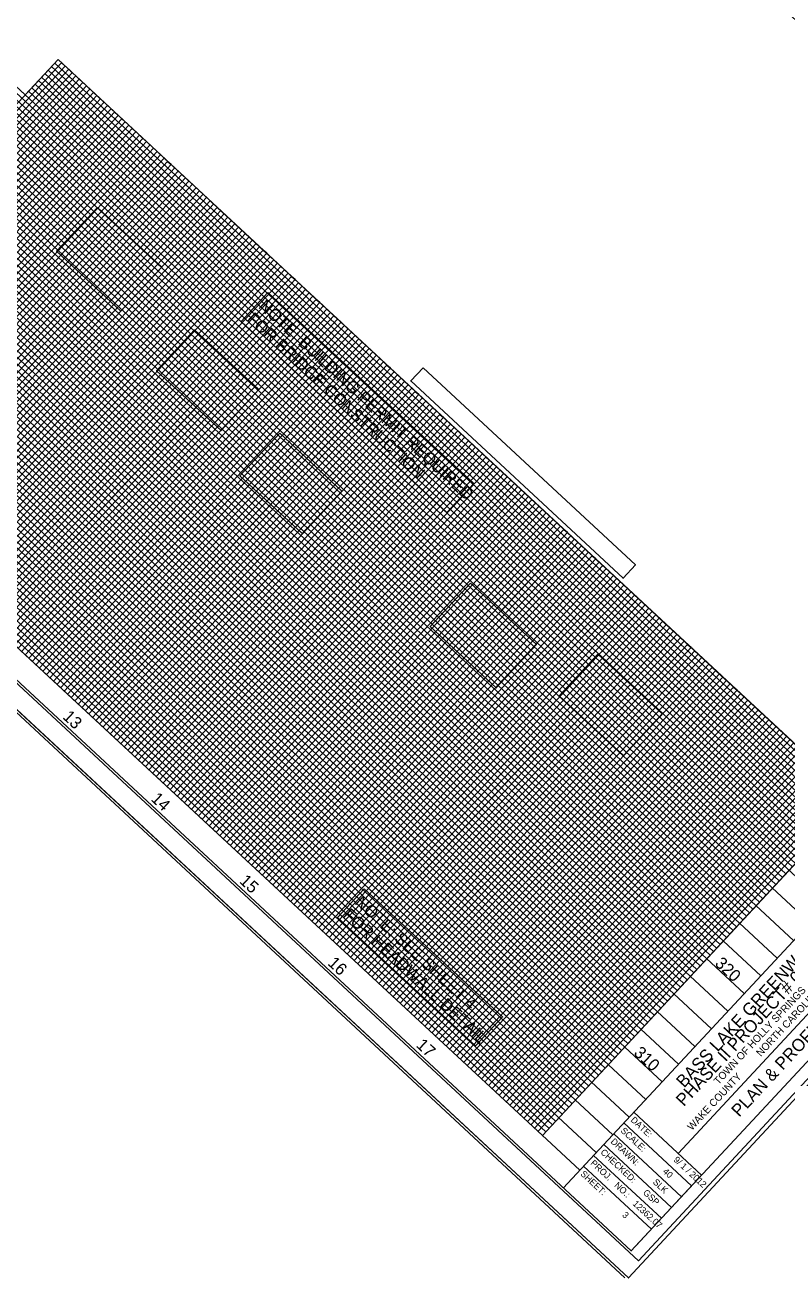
# Model space of a CAD drawing. Extents: x 2057696 to 2061410, y 685900 to 689434.
# Drawn here: x 2058183 to 2058814, y 687875 to 688913 of the extents above; entities that cross this region are included whole.
import ezdxf

# ---------------------------------------------------------------- set-up
doc = ezdxf.new("R2010")
doc.units = 0
for name, color, linetype in [('Default', 7, 'Continuous'), ('Exist Vertical Profile Vertical Axis Label', 7, 'Continuous'), ('Prop Approach Slab', 7, 'Continuous'), ('Prop Boundary Buffer Zone 2', 7, 'Continuous'), ('Prop SS Cut Line', 7, 'Continuous'), ('Prop Vertical Profile Curve Label', 7, 'Continuous'), ('Sheet Cutting Line CELL', 7, 'Continuous'), ('Sheet Plan CELL', 7, 'Continuous'), ('Sheet Plot Border Inside CELL', 7, 'Continuous'), ('Sheet Plot Border Outside CELL', 7, 'Continuous'), ('Sheet Profile Grid Major CELL', 7, 'Continuous')]:
    doc.layers.add(name, color=color, linetype=linetype)

msp = doc.modelspace()

# ---------------------------------------------------------------- linework, layer by layer
at = {"layer": 'Default'}
for p, q in [((2058239.6, 688857.6), (2058268.9, 688830.4)), ((2058268.9, 688830.4), (2058010.2, 688552)), ((2058298.2, 688803.1), (2058327.5, 688775.9)), ((2057696.3, 688791.9), (2058682.8, 687875)), ((2058342.2, 688762.3), (2058083.5, 688484)), ((2058356.8, 688748.7), (2058386.1, 688721.4)), ((2057754, 688735.6), (2058679.9, 687875)), ((2057806.1, 688714.4), (2058685.1, 687897.4)), ((2058415.4, 688694.2), (2058399.7, 688677.3)), ((2058415.4, 688694.2), (2058444.7, 688667)), ((2058377.4, 688653.3), (2058356.1, 688630.4)), ((2058474, 688639.7), (2058503.3, 688612.5)), ((2058488.7, 688626.1), (2058472.9, 688609.2)), ((2058324.6, 688596.5), (2058156.7, 688415.9)), ((2058450.5, 688585.1), (2058419.2, 688551.5)), ((2058532.6, 688585.3), (2058561.9, 688558.1)), ((2059200.9, 688564.9), (2058628.8, 687949.4)), ((2058561.9, 688558.1), (2058546.2, 688541.1)), ((2058591.2, 688530.8), (2058620.5, 688503.6)), ((2058386.4, 688516.1), (2058229.9, 688347.8)), ((2058523.9, 688517.2), (2058303.2, 688279.7)), ((2059257, 688512.7), (2058684.9, 687897.2)), ((2058635.1, 688490), (2058577, 688427.4)), ((2058649.8, 688476.4), (2058679.1, 688449.1)), ((2058708.4, 688421.9), (2058669.9, 688380.5)), ((2058708.4, 688421.9), (2058737.7, 688394.7)), ((2058543.7, 688391.6), (2058376.4, 688211.6)), ((2058781.6, 688353.8), (2058556.5, 688111.6)), ((2058637.8, 688346), (2058483.3, 688179.7)), ((2058854.9, 688285.7), (2058596.2, 688007.4)), ((2058461, 688155.7), (2058449.7, 688143.6)), ((2058724.1, 687978.2), (2058897.9, 688165.2)), ((2058533.8, 688087.2), (2058522.9, 688075.5)), ((2058743.4, 687960.2), (2058687.3, 688012.4)), ((2058735.1, 687951.2), (2058679, 688003.4)), ((2058726.8, 687942.3), (2058670.7, 687994.4)), ((2058718.5, 687933.3), (2058662.4, 687985.5)), ((2058710.2, 687924.4), (2058654, 687976.5)), ((2058701.8, 687915.4), (2058645.7, 687967.6)), ((2058743.4, 687960.2), (2058688.9, 687901.7))]:
    msp.add_line(p, q, dxfattribs=at)
for points in [[(2057696.3, 688791.9), (2058682.8, 687875), (2059279.2, 688516.6), (2058292.7, 689433.5)], [(2057714.8, 688796.5), (2058691.1, 687889.2), (2059265.7, 688507.4), (2058289.4, 689414.7)]]:
    msp.add_lwpolyline(points, close=True, dxfattribs=at)
at = {"layer": 'Exist Vertical Profile Vertical Axis Label'}
for points in [[(2057954.5, 688603.8), (2058213.2, 688882.1), (2058216.2, 688879.4), (2057957.5, 688601.1)], [(2057960.4, 688598.3), (2058219.1, 688876.7), (2058222, 688873.9), (2057963.3, 688595.6)], [(2057969.2, 688590.2), (2058227.9, 688868.5), (2058230.8, 688865.8), (2057972.1, 688587.4)], [(2057975, 688584.7), (2058233.8, 688863.1), (2058236.7, 688860.3), (2057978, 688582)], [(2057983.8, 688576.5), (2058242.5, 688854.9), (2058245.5, 688852.2), (2057986.8, 688573.8)], [(2057989.7, 688571.1), (2058248.4, 688849.4), (2058251.3, 688846.7), (2057992.6, 688568.4)], [(2057998.5, 688562.9), (2058257.2, 688841.3), (2058260.1, 688838.5), (2058001.4, 688560.2)], [(2058004.3, 688557.5), (2058263.1, 688835.8), (2058266, 688833.1), (2058007.3, 688554.8)], [(2058013.1, 688549.3), (2058271.8, 688827.7), (2058274.8, 688824.9), (2058016.1, 688546.6)], [(2058019, 688543.9), (2058277.7, 688822.2), (2058280.6, 688819.5), (2058021.9, 688541.1)], [(2058027.8, 688535.7), (2058286.5, 688814), (2058289.4, 688811.3), (2058030.7, 688533)], [(2058033.6, 688530.3), (2058292.3, 688808.6), (2058295.3, 688805.9), (2058036.6, 688527.5)], [(2058042.4, 688522.1), (2058301.1, 688800.4), (2058304.1, 688797.7), (2058045.4, 688519.4)], [(2058048.3, 688516.6), (2058307, 688795), (2058309.9, 688792.3), (2058051.2, 688513.9)], [(2058057.1, 688508.5), (2058315.8, 688786.8), (2058318.7, 688784.1), (2058060, 688505.7)], [(2058062.9, 688503), (2058321.6, 688781.4), (2058324.6, 688778.6), (2058065.9, 688500.3)], [(2058071.7, 688494.9), (2058330.4, 688773.2), (2058333.4, 688770.5), (2058074.7, 688492.1)], [(2058077.6, 688489.4), (2058336.3, 688767.7), (2058339.2, 688765), (2058080.5, 688486.7)], [(2058086.4, 688481.2), (2058345.1, 688759.6), (2058348, 688756.8), (2058089.3, 688478.5)], [(2058092.2, 688475.8), (2058350.9, 688754.1), (2058353.9, 688751.4), (2058095.2, 688473.1)], [(2058101, 688467.6), (2058359.7, 688746), (2058362.7, 688743.2), (2058104, 688464.9)], [(2058106.9, 688462.2), (2058365.6, 688740.5), (2058368.5, 688737.8), (2058109.8, 688459.4)], [(2058115.7, 688454), (2058374.4, 688732.3), (2058377.3, 688729.6), (2058118.6, 688451.3)], [(2058121.5, 688448.6), (2058380.2, 688726.9), (2058383.2, 688724.2), (2058124.5, 688445.8)], [(2058130.3, 688440.4), (2058389, 688718.7), (2058392, 688716), (2058133.3, 688437.7)], [(2058136.2, 688434.9), (2058394.9, 688713.3), (2058397.8, 688710.6), (2058139.1, 688432.2)], [(2058145, 688426.8), (2058403.7, 688705.1), (2058406.6, 688702.4), (2058147.9, 688424)], [(2058150.8, 688421.3), (2058409.5, 688699.7), (2058412.5, 688696.9), (2058153.8, 688418.6)], [(2058159.6, 688413.2), (2058418.3, 688691.5), (2058421.3, 688688.8), (2058162.6, 688410.4)], [(2058165.5, 688407.7), (2058424.2, 688686), (2058427.1, 688683.3), (2058168.4, 688405)], [(2058174.3, 688399.5), (2058433, 688677.9), (2058435.9, 688675.2), (2058177.2, 688396.8)], [(2058180.1, 688394.1), (2058438.8, 688672.4), (2058441.8, 688669.7), (2058183.1, 688391.4)], [(2058188.9, 688385.9), (2058447.6, 688664.3), (2058450.6, 688661.5), (2058191.9, 688383.2)], [(2058194.8, 688380.5), (2058453.5, 688658.8), (2058456.4, 688656.1), (2058197.7, 688377.8)], [(2058203.6, 688372.3), (2058462.3, 688650.6), (2058465.2, 688647.9), (2058206.5, 688369.6)], [(2058209.4, 688366.9), (2058468.1, 688645.2), (2058471.1, 688642.5), (2058212.4, 688364.1)], [(2058218.2, 688358.7), (2058476.9, 688637), (2058479.9, 688634.3), (2058221.2, 688356)], [(2058224.1, 688353.2), (2058482.8, 688631.6), (2058485.7, 688628.9), (2058227, 688350.5)], [(2058232.9, 688345.1), (2058491.6, 688623.4), (2058494.5, 688620.7), (2058235.8, 688342.4)], [(2058238.7, 688339.6), (2058497.4, 688618), (2058500.4, 688615.2), (2058241.7, 688336.9)], [(2058247.5, 688331.5), (2058506.2, 688609.8), (2058509.2, 688607.1), (2058250.5, 688328.7)], [(2058253.4, 688326), (2058512.1, 688604.3), (2058515, 688601.6), (2058256.3, 688323.3)], [(2058262.2, 688317.8), (2058520.9, 688596.2), (2058523.8, 688593.5), (2058265.1, 688315.1)], [(2058268, 688312.4), (2058526.7, 688590.7), (2058529.7, 688588), (2058271, 688309.7)], [(2058276.8, 688304.2), (2058535.5, 688582.6), (2058538.5, 688579.8), (2058279.8, 688301.5)], [(2058282.7, 688298.8), (2058541.4, 688577.1), (2058544.3, 688574.4), (2058285.6, 688296.1)], [(2058291.5, 688290.6), (2058550.2, 688568.9), (2058553.1, 688566.2), (2058294.4, 688287.9)], [(2058297.3, 688285.2), (2058556, 688563.5), (2058559, 688560.8), (2058300.3, 688282.4)], [(2058306.1, 688277), (2058564.8, 688555.3), (2058567.8, 688552.6), (2058309.1, 688274.3)], [(2058312, 688271.5), (2058570.7, 688549.9), (2058573.6, 688547.2), (2058314.9, 688268.8)], [(2058320.8, 688263.4), (2058579.5, 688541.7), (2058582.4, 688539), (2058323.7, 688260.7)], [(2058326.6, 688257.9), (2058585.3, 688536.3), (2058588.3, 688533.5), (2058329.6, 688255.2)], [(2058335.4, 688249.8), (2058594.1, 688528.1), (2058597.1, 688525.4), (2058338.3, 688247)], [(2058341.3, 688244.3), (2058600, 688522.7), (2058602.9, 688519.9), (2058344.2, 688241.6)], [(2058350.1, 688236.1), (2058608.8, 688514.5), (2058611.7, 688511.8), (2058353, 688233.4)], [(2058355.9, 688230.7), (2058614.6, 688509), (2058617.6, 688506.3), (2058358.9, 688228)], [(2058364.7, 688222.5), (2058623.4, 688500.9), (2058626.4, 688498.1), (2058367.6, 688219.8)], [(2058370.6, 688217.1), (2058629.3, 688495.4), (2058632.2, 688492.7), (2058373.5, 688214.4)], [(2058379.4, 688208.9), (2058638.1, 688487.2), (2058641, 688484.5), (2058382.3, 688206.2)], [(2058385.2, 688203.5), (2058643.9, 688481.8), (2058646.9, 688479.1), (2058388.2, 688200.7)], [(2058394, 688195.3), (2058652.7, 688473.6), (2058655.7, 688470.9), (2058396.9, 688192.6)], [(2058399.9, 688189.9), (2058658.6, 688468.2), (2058661.5, 688465.5), (2058402.8, 688187.1)], [(2058408.7, 688181.7), (2058667.4, 688460), (2058670.3, 688457.3), (2058411.6, 688179)], [(2058414.5, 688176.2), (2058673.2, 688454.6), (2058676.2, 688451.8), (2058417.5, 688173.5)], [(2058423.3, 688168.1), (2058682, 688446.4), (2058685, 688443.7), (2058426.2, 688165.3)], [(2058429.2, 688162.6), (2058687.9, 688441), (2058690.8, 688438.2), (2058432.1, 688159.9)], [(2058438, 688154.4), (2058696.7, 688432.8), (2058699.6, 688430.1), (2058440.9, 688151.7)], [(2058443.8, 688149), (2058702.5, 688427.3), (2058705.5, 688424.6), (2058446.8, 688146.3)], [(2058452.6, 688140.8), (2058711.3, 688419.2), (2058714.2, 688416.4), (2058455.5, 688138.1)], [(2058458.5, 688135.4), (2058717.2, 688413.7), (2058720.1, 688411), (2058461.4, 688132.7)], [(2058467.3, 688127.2), (2058726, 688405.6), (2058728.9, 688402.8), (2058470.2, 688124.5)], [(2058473.1, 688121.8), (2058731.8, 688400.1), (2058734.8, 688397.4), (2058476.1, 688119)], [(2058481.9, 688113.6), (2058740.6, 688391.9), (2058743.5, 688389.2), (2058484.8, 688110.9)], [(2058487.8, 688108.2), (2058746.5, 688386.5), (2058749.4, 688383.8), (2058490.7, 688105.4)], [(2058496.6, 688100), (2058755.3, 688378.3), (2058758.2, 688375.6), (2058499.5, 688097.3)], [(2058502.4, 688094.5), (2058761.1, 688372.9), (2058764.1, 688370.2), (2058505.4, 688091.8)], [(2058511.2, 688086.4), (2058769.9, 688364.7), (2058772.8, 688362), (2058514.1, 688083.6)], [(2058517.1, 688080.9), (2058775.8, 688359.3), (2058778.7, 688356.5), (2058520, 688078.2)], [(2058525.9, 688072.8), (2058784.6, 688351.1), (2058787.5, 688348.4), (2058528.8, 688070)], [(2058531.7, 688067.3), (2058790.4, 688345.6), (2058793.4, 688342.9), (2058534.6, 688064.6)], [(2058540.5, 688059.1), (2058799.2, 688337.5), (2058802.1, 688334.7), (2058543.4, 688056.4)], [(2058546.4, 688053.7), (2058805.1, 688332), (2058808, 688329.3), (2058549.3, 688051)], [(2058555.2, 688045.5), (2058813.9, 688323.9), (2058816.8, 688321.1), (2058558.1, 688042.8)], [(2058561, 688040.1), (2058819.7, 688318.4), (2058822.7, 688315.7), (2058563.9, 688037.4)], [(2058569.8, 688031.9), (2058828.5, 688310.2), (2058831.4, 688307.5), (2058572.7, 688029.2)], [(2058575.7, 688026.5), (2058834.4, 688304.8), (2058837.3, 688302.1), (2058578.6, 688023.7)], [(2058584.5, 688018.3), (2058843.2, 688296.6), (2058846.1, 688293.9), (2058587.4, 688015.6)], [(2058590.3, 688012.8), (2058849, 688291.2), (2058852, 688288.5), (2058593.2, 688010.1)], [(2058599.1, 688004.7), (2058857.8, 688283), (2058860.7, 688280.3), (2058602, 688001.9)], [(2058605, 687999.2), (2058863.7, 688277.6), (2058866.6, 688274.8), (2058607.9, 687996.5)]]:
    msp.add_lwpolyline(points, dxfattribs=at)
at = {"layer": 'Prop Approach Slab'}
msp.add_lwpolyline([(2058512.7, 688629.4), (2058688.6, 688465.9), (2058678.4, 688454.9), (2058502.5, 688618.4)], close=True, dxfattribs=at)
at = {"layer": 'Prop Boundary Buffer Zone 2'}
for p, q in [((2058860.5, 688198.6), (2058037.6, 688963.4)), ((2058833.2, 688169.3), (2058010.4, 688934.1)), ((2058806, 688140), (2057983.2, 688904.8)), ((2058210.3, 688884.8), (2057951.6, 688606.5)), ((2058778.8, 688110.7), (2057955.9, 688875.5)), ((2058887.7, 688227.9), (2058196.7, 688870.2)), ((2057980.9, 688579.3), (2058239.6, 688857.6)), ((2058751.5, 688081.4), (2057928.7, 688846.2)), ((2058268.9, 688830.4), (2058010.2, 688552)), ((2058724.3, 688052.1), (2057901.5, 688816.9)), ((2058039.5, 688524.8), (2058298.2, 688803.1)), ((2058697.1, 688022.8), (2057874.2, 688787.6)), ((2058327.5, 688775.9), (2058068.8, 688497.6)), ((2058669.8, 687993.5), (2057847, 688758.3)), ((2058098.1, 688470.3), (2058356.8, 688748.7)), ((2058386.1, 688721.4), (2058127.4, 688443.1)), ((2058156.7, 688415.9), (2058415.4, 688694.2)), ((2058444.7, 688667), (2058186, 688388.6)), ((2058215.3, 688361.4), (2058474, 688639.7)), ((2058503.3, 688612.5), (2058244.6, 688334.2)), ((2058273.9, 688306.9), (2058532.6, 688585.3)), ((2058561.9, 688558.1), (2058303.2, 688279.7)), ((2058332.5, 688252.5), (2058591.2, 688530.8)), ((2058620.5, 688503.6), (2058361.8, 688225.3)), ((2058391.1, 688198), (2058649.8, 688476.4)), ((2058679.1, 688449.1), (2058420.4, 688170.8)), ((2058449.7, 688143.6), (2058708.4, 688421.9)), ((2058737.7, 688394.7), (2058479, 688116.3)), ((2058508.3, 688089.1), (2058767, 688367.4)), ((2058796.3, 688340.2), (2058537.6, 688061.9)), ((2058566.9, 688034.6), (2058825.6, 688313)), ((2058854.9, 688285.7), (2058596.2, 688007.4))]:
    msp.add_line(p, q, dxfattribs=at)
for points in [[(2057966.3, 688592.9), (2058225, 688871.2), (2058254.3, 688844), (2057995.6, 688565.7)], [(2058024.9, 688538.4), (2058283.6, 688816.8), (2058312.9, 688789.5), (2058054.2, 688511.2)], [(2058083.5, 688484), (2058342.2, 688762.3), (2058371.5, 688735.1), (2058112.7, 688456.7)], [(2058142, 688429.5), (2058400.8, 688707.8), (2058430.1, 688680.6), (2058171.3, 688402.3)], [(2058200.6, 688375), (2058459.4, 688653.4), (2058488.7, 688626.1), (2058229.9, 688347.8)], [(2058259.2, 688320.6), (2058517.9, 688598.9), (2058547.2, 688571.7), (2058288.5, 688293.3)], [(2058317.8, 688266.1), (2058576.5, 688544.4), (2058605.8, 688517.2), (2058347.1, 688238.9)], [(2058376.4, 688211.6), (2058635.1, 688490), (2058664.4, 688462.7), (2058405.7, 688184.4)], [(2058435, 688157.2), (2058693.7, 688435.5), (2058723, 688408.3), (2058464.3, 688129.9)], [(2058493.6, 688102.7), (2058752.3, 688381), (2058781.6, 688353.8), (2058522.9, 688075.5)], [(2058552.2, 688048.2), (2058810.9, 688326.6), (2058840.2, 688299.3), (2058581.5, 688021)]]:
    msp.add_lwpolyline(points, dxfattribs=at)
at = {"layer": 'Prop SS Cut Line'}
msp.add_line((2058642.6, 687964.2), (2057819.8, 688729), dxfattribs=at)
at = {"layer": 'Prop Vertical Profile Curve Label'}
for points in [[(2058210.3, 688884.8), (2058901.3, 688242.6), (2059147.2, 688507.2), (2059089, 688561.3), (2059142.6, 688619), (2058378, 689329.7), (2058078.5, 689007.4), (2058137.1, 688952.9)], [(2058137.1, 688952.9), (2058107.8, 688980.2), (2057849.1, 688701.8), (2058611.6, 687993), (2058870.3, 688271.4), (2058210.3, 688884.8)], [(2058210.3, 688884.8), (2058183.1, 688855.5), (2058109.8, 688923.6), (2058137.1, 688952.9)], [(2058137.1, 688952.9), (2058109.8, 688923.6), (2058183.1, 688855.5), (2058210.3, 688884.8)]]:
    msp.add_lwpolyline(points, dxfattribs=at)
at = {"layer": 'Sheet Cutting Line CELL'}
for p, q in [((2058846.8, 688184), (2058024, 688948.8)), ((2058819.6, 688154.7), (2057996.8, 688919.5)), ((2058874.1, 688213.3), (2058109.8, 688923.6)), ((2058792.4, 688125.4), (2057969.5, 688890.2)), ((2058901.3, 688242.6), (2058210.3, 688884.8)), ((2058765.1, 688096.1), (2057942.3, 688860.9)), ((2058737.9, 688066.8), (2057915.1, 688831.6)), ((2058710.7, 688037.5), (2057887.8, 688802.3)), ((2058683.5, 688008.2), (2057860.6, 688773)), ((2058656.2, 687978.9), (2057833.4, 688743.7)), ((2058611.6, 687993), (2058870.3, 688271.4))]:
    msp.add_line(p, q, dxfattribs=at)
at = {"layer": 'Sheet Plot Border Inside CELL'}
for p, q in [((2058837.6, 688236.2), (2058075.1, 688945)), ((2058840.4, 688239.2), (2058077.8, 688947.9)), ((2058832.2, 688230.4), (2058069.6, 688939.1)), ((2058834.9, 688233.3), (2058072.4, 688942.1)), ((2058818.6, 688215.7), (2058056, 688924.5)), ((2058821.3, 688218.6), (2058058.8, 688927.4)), ((2058824, 688221.6), (2058061.5, 688930.3)), ((2058826.7, 688224.5), (2058064.2, 688933.3)), ((2058810.4, 688206.9), (2058047.9, 688915.7)), ((2058813.1, 688209.9), (2058050.6, 688918.6)), ((2058799.5, 688195.2), (2058037, 688904)), ((2058805, 688201.1), (2058042.4, 688909.8)), ((2058807.7, 688204), (2058045.1, 688912.8)), ((2058791.3, 688186.4), (2058028.8, 688895.2)), ((2058794.1, 688189.3), (2058031.5, 688898.1)), ((2058796.8, 688192.3), (2058034.2, 688901)), ((2058780.5, 688174.7), (2058017.9, 688883.5)), ((2058783.2, 688177.6), (2058020.6, 688886.4)), ((2058785.9, 688180.6), (2058023.3, 688889.3)), ((2058772.3, 688165.9), (2058009.7, 688874.7)), ((2058777.7, 688171.8), (2058015.2, 688880.5)), ((2058859.4, 688259.7), (2058199.4, 688873.1)), ((2058862.2, 688262.6), (2058202.1, 688876)), ((2058864.9, 688265.5), (2058204.9, 688879)), ((2058867.6, 688268.5), (2058207.6, 688881.9)), ((2058764.1, 688157.1), (2058001.6, 688865.9)), ((2058766.8, 688160), (2058004.3, 688868.8)), ((2058769.6, 688163), (2058007, 688871.7)), ((2058851.3, 688250.9), (2058191.3, 688864.3)), ((2058854, 688253.8), (2058194, 688867.3)), ((2058750.5, 688142.5), (2057987.9, 688851.2)), ((2058753.2, 688145.4), (2057990.7, 688854.2)), ((2058755.9, 688148.3), (2057993.4, 688857.1)), ((2058758.7, 688151.3), (2057996.1, 688860)), ((2058845.8, 688245), (2058185.8, 688858.5)), ((2058848.5, 688247.9), (2058188.5, 688861.4)), ((2058742.3, 688133.7), (2057979.8, 688842.4)), ((2058745.1, 688136.6), (2057982.5, 688845.4)), ((2058731.4, 688122), (2057968.9, 688830.7)), ((2058736.9, 688127.8), (2057974.3, 688836.6)), ((2058739.6, 688130.7), (2057977.1, 688839.5)), ((2058723.3, 688113.2), (2057960.7, 688821.9)), ((2058726, 688116.1), (2057963.4, 688824.9)), ((2058728.7, 688119), (2057966.2, 688827.8)), ((2058712.4, 688101.5), (2057949.8, 688810.2)), ((2058715.1, 688104.4), (2057952.5, 688813.2)), ((2058717.8, 688107.3), (2057955.3, 688816.1)), ((2058704.2, 688092.7), (2057941.7, 688801.4)), ((2058709.7, 688098.5), (2057947.1, 688807.3)), ((2058696, 688083.9), (2057933.5, 688792.6)), ((2058698.8, 688086.8), (2057936.2, 688795.6)), ((2058701.5, 688089.7), (2057938.9, 688798.5)), ((2058685.1, 688072.2), (2057922.6, 688780.9)), ((2058687.9, 688075.1), (2057925.3, 688783.9)), ((2058690.6, 688078), (2057928, 688786.8)), ((2058674.2, 688060.4), (2057911.7, 688769.2)), ((2058677, 688063.4), (2057914.4, 688772.1)), ((2058682.4, 688069.2), (2057919.9, 688778)), ((2058668.8, 688054.6), (2057906.3, 688763.3)), ((2058671.5, 688057.5), (2057909, 688766.3)), ((2058655.2, 688039.9), (2057892.6, 688748.7)), ((2058657.9, 688042.9), (2057895.4, 688751.6)), ((2058660.6, 688045.8), (2057898.1, 688754.6)), ((2058663.4, 688048.7), (2057900.8, 688757.5)), ((2058644.3, 688028.2), (2057881.7, 688737)), ((2058647, 688031.1), (2057884.5, 688739.9)), ((2058649.7, 688034.1), (2057887.2, 688742.8)), ((2058636.1, 688019.4), (2057873.6, 688728.2)), ((2058641.6, 688025.3), (2057879, 688734)), ((2058628, 688010.6), (2057865.4, 688719.4)), ((2058630.7, 688013.6), (2057868.1, 688722.3)), ((2058633.4, 688016.5), (2057870.8, 688725.3)), ((2058617.1, 687998.9), (2057854.5, 688707.7)), ((2058619.8, 688001.8), (2057857.2, 688710.6)), ((2058622.5, 688004.8), (2057860, 688713.5)), ((2058614.3, 687996), (2057851.8, 688704.7))]:
    msp.add_line(p, q, dxfattribs=at)
at = {"layer": 'Sheet Profile Grid Major CELL'}
for points in [[(2058242.9, 688762.3), (2058296.2, 688712.7), (2058262.4, 688676.3), (2058209.1, 688725.9)], [(2058384.2, 688691.7), (2058554.6, 688533.3), (2058532.4, 688509.3), (2058361.9, 688667.7)], [(2058323.4, 688660.7), (2058376.7, 688611.2), (2058345.3, 688577.3), (2058291.9, 688626.9)], [(2058393.9, 688575.1), (2058445.3, 688527.2), (2058412.5, 688491.9), (2058361, 688539.7)], [(2058551.9, 688450.8), (2058606.6, 688399.9), (2058573.3, 688364), (2058518.6, 688414.9)], [(2058657.5, 688392), (2058710.8, 688342.4), (2058678.7, 688307.9), (2058625.4, 688357.5)], [(2058464, 688197.6), (2058578.5, 688091.3), (2058556.2, 688067.3), (2058441.7, 688173.7)]]:
    msp.add_lwpolyline(points, close=True, dxfattribs=at)

# ---------------------------------------------------------------- texts
at = {"layer": 'Default'}
for s, height, rotation, p in [('WAKE COUNTY          NORTH CAROLINA', 6.129, 47.0934, (2058735.4, 687996.7)), ('TOWN OF HOLLY SPRINGS', 6.129, 47.0934, (2058757.4, 688034.7)), ('DATE:', 5.35, 317.0934, (2058684.2, 688005.3)), ('DRAWN:', 5.35, 317.0934, (2058667.6, 687987.4)), ('SCALE:', 5.35, 317.0934, (2058675.9, 687996.4)), ('CHECKED:', 5.35, 317.0934, (2058659.2, 687978.5)), ('PROJ.   NO.:', 5.347, 317.0934, (2058650.9, 687969.5)), ('9/ 1 / 2012', 5.347, 317.0934, (2058719.7, 687972.3)), ('SHEET:        ', 5.347, 317.0934, (2058642.6, 687960.6)), ('40', 5.35, 317.0934, (2058710.8, 687962.6)), ('GSP', 5.35, 317.0934, (2058694.4, 687945)), ('SLK', 5.35, 317.0934, (2058702.6, 687953.8)), ('12362.07', 5.35, 317.0934, (2058685.9, 687935.9)), ('3', 5.35, 317.0934, (2058677.2, 687926.5))]:
    msp.add_text(s, height=height, rotation=rotation, dxfattribs=at).set_placement(p)
at = {"layer": 'Prop Approach Slab'}
for s, p in [('NOTE: BUILDING PERMIT REQUIRED ', (2058375.7, 688679.5)), ('FOR BRIDGE CONSTRUCTION', (2058365.9, 688668.9)), ('NOTE: SEE SHEET 4', (2058455.5, 688185.4)), ('FOR HEADWALL DETAIL', (2058445.7, 688174.9))]:
    msp.add_text(s, height=10, rotation=317.0934, dxfattribs=at).set_placement(p)
at = {"layer": 'Sheet Cutting Line CELL'}
for s, p in [('PHASE II PROJECT# 08-037', (2058728.7, 688016.5)), ('BASS LAKE GREENWAY', (2058728.9, 688032)), ('PLAN & PROFILE', (2058774.6, 688007.7))]:
    msp.add_text(s, height=10.342, rotation=47.0934, dxfattribs=at).set_placement(p)
at = {"layer": 'Sheet Plan CELL'}
for s, p in [('320', (2058753.8, 688134.7)), ('310', (2058686.6, 688060.6))]:
    msp.add_text(s, height=10, rotation=317.0934, dxfattribs=at).set_placement(p)
at = {"layer": 'Sheet Plot Border Outside CELL'}
for s, p in [('13', (2058213.5, 688339.2)), ('14', (2058286.6, 688271.2)), ('15', (2058359.9, 688203.1)), ('16', (2058433.1, 688135)), ('17', (2058506.3, 688067.1))]:
    msp.add_text(s, height=10, rotation=317.0934, dxfattribs=at).set_placement(p)

doc.saveas('drawing.dxf')
